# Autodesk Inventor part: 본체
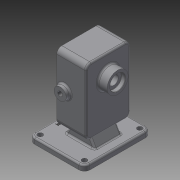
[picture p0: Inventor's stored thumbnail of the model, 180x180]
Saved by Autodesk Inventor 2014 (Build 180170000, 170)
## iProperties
Created: 2020-04
Part Number: 본체
Material: Generic
Document SubType Name: Modeling
Designer: kh
Density: 1 g/cm^3
Appearance: Default
Mass: 544.812 g
Surface Area: 819.925 cm^2
Volume: 544.812 cm^3
Author: kh
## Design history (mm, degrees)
sketch "스케치1"
  geometry: L1 (-50, -60)-(50, -60); L2 (50, -60)-(50, 60); L3 (50, 60)-(-50, 60); L4 (-50, 60)-(-50, -60); L5 (-50, -60)-(50, 60); L6 (50, -60)-(-50, 60); 1 further point
  constraints: 12 end point, 2 midpoint, 2 parallel, 1 horizontal, 1 perpendicular
  dimensions: "d0" = 100 distance of L3.end L2.end; "d1" = 120 distance of L2.end L1.end
extrude "돌출1" new body sketch "스케치1" distance "d2" = 10; taper "d3" = 0 deg
node "작업 평면1"
sketch "스케치3"
  geometry: L1 (-30, 20)-(-150, 20); L2 (-150, 20)-(-150, 100); L3 (-150, 100)-(-30, 100); L4 (-30, 100)-(-30, 20); L5 (-90, 100)-(-90, 20); L6 (0, 60)-(-22.355, 60); L7 (0, 120)-(0, 0) reference; 1 further point
  constraints: 12 end point, 3 midpoint, 2 parallel, 2 perpendicular, 1 horizontal, 1 point on line
  dimensions: "d10" = 120 distance of L2.end L3.end; "d11" = 80 distance of L1.end L2.end; "d12" = 90 distance from line of L7 L5.start
extrude "돌출3" join sketch "스케치3" distance "d13" = 53; taper "d14" = 0 deg
sketch "스케치4"
  geometry: L1 (-30, 20)-(-150, 20) reference; L2 (-30, 100)-(-30, 20) reference; L3 (-150, 100)-(-30, 100) reference; L4 (-150, 20)-(-150, 100) reference; L5 (0, 60)-(-21.925, 60); L6 (-90, 100)-(-90, 20); C1 r 19 at (-112, 60)
  constraints: 4 end point, 2 midpoint, 1 centre point, 1 perpendicular, 1 point on line
  dimensions: "d15" = 38 diameter of C1; "d16" = 22 distance from line of L6 C1.centre
extrude "돌출4" join sketch "스케치4" stored distance "d17" = 53; taper "d18" = 0 deg
sketch "스케치5"
  geometry: L1 (112, 60)-(68, 60); L2 (112, 84)-(68, 84); L3 (68, 36)-(112, 36); C1 r 19 at (112, 60) reference; A1 r 24 centre (112, 60) between (112, 36) and (112, 84); A2 r 24 centre (68, 60) between (68, 84) and (68, 36); 2 further points
  constraints: 8 end point, 4 point on circle, 4 tangent, 2 centre point, 1 horizontal, 1 midpoint, 1 parallel
  dimensions: "d19" = 44 distance of L1.start L1.end; "d20" = 24 radius of A1
extrude "돌출5" cut sketch "스케치5" distance "d21" = 29; taper "d22" = 0 deg
sketch "스케치6"
  geometry: L1 (68, 84)-(112, 84) reference; L2 (112, 36)-(68, 36) reference; C1 r 12.5 at (112, 60); C2 r 12.5 at (68, 60); A1 r 24 centre (68, 60) between (68, 84) and (68, 36) reference; A2 r 24 centre (112, 60) between (112, 36) and (112, 84) reference; 1 further point
  constraints: 2 centre point, 2 coincident
  dimensions: "d23" = 25 diameter of C1; "d24" = 25 diameter of C2
extrude "돌출6" cut sketch "스케치6" distance "d25" = 15; taper "d26" = 0 deg
sketch "스케치8"
  geometry: C1 r 19 at (0, 0) reference; C2 r 14 at (0, 0); 1 further point
  constraints: 1 centre point, 1 coincident
  dimensions: "d28" = 28 diameter of C2
extrude "돌출7" cut sketch "스케치8" distance "d29" = 7.3; taper "d30" = 0 deg
sketch "스케치9"
  geometry: C1 r 14 at (0, 0) reference; C2 r 8.5 at (0, 0); 1 further point
  constraints: 1 centre point, 1 coincident
  dimensions: "d31" = 17 diameter of C2
extrude "돌출8" cut sketch "스케치9" stored distance "d32" = 7.3; taper "d33" = 0 deg
sketch "스케치12"
  geometry: L1 (33, -40)-(33, 40) reference; L2 (33, 40)-(-20, 40) reference; L3 (-20, -40)-(-20, 40) reference; L4 (33, -40)-(-20, -40) reference; L5 (6, -24)-(7, -24); L6 (7, -24)-(7, 24); L7 (7, 24)-(6, 24); L8 (6, 24)-(6, -24); L9 (0, 0)-(-6.48, 0); L10 (6.5, 40)-(6.5, 35.569); 2 further points
  constraints: 12 end point, 3 midpoint, 3 perpendicular, 2 parallel, 2 point on line, 1 horizontal
  dimensions: "d40" = 1 distance of L7.end L6.end; "d41" = 48 distance of L6.end L5.end
extrude "돌출10" join sketch "스케치12" stored distance "d42" = 7.3; taper "d43" = 0 deg
sketch "스케치13"
  geometry: L1 (50, 0)-(-50, 0) reference; L2 (-50, 0)-(-50, 10) reference; L3 (50, 10)-(-50, 10) reference; L4 (50, 0)-(50, 10) reference; L5 (-33, 30)-(-33, 150) reference; L6 (-33, 150)-(20, 150) reference; L7 (20, 30)-(20, 150) reference; L8 (-33, 30)-(20, 30) reference; L9 (20, 10)-(11.709, 24.361); L10 (-33, 10)-(-25.418, 23.132); 1 further point
  constraints: 4 end point, 2 point on line
  dimensions: "d44" = 60 deg angle of L3 L9; "d46" = 60 deg angle of L3 L10; "d47" = 17 distance from line of L10.start L2; "d48" = 53 distance of L9.start L10.start
  node "투영된 루프8"
  node "투영된 루프9"
feature "리브1" dims "d49" = 1, "d50" = 48, "d51" = 0, "d52" = 0, "d53" = 1, "d54" = 1
feature "리브2" dims "d55" = 1, "d56" = 48, "d57" = 0, "d58" = 0, "d59" = 1, "d60" = 1
node "작업 평면3"
sketch "스케치14"
  geometry: L1 (0, 0)-(0, 120) reference; L2 (0, 120)-(-53, 120) reference; L3 (-53, 0)-(-53, 120) reference; L4 (0, 0)-(-53, 0) reference; L5 (-53, 60)-(-47.567, 60); C1 r 11 at (-39, 60); 1 further point
  constraints: 2 end point, 1 centre point, 1 midpoint, 1 parallel, 1 point on line
  dimensions: "d62" = 22 diameter of C1; "d63" = 14 distance from line of C1.centre L3
extrude "돌출11" join sketch "스케치14" stored distance "d64" = 7.3; taper "d65" = 0 deg
sketch "스케치15"
  geometry: C1 r 11 at (0, 0) reference; 2 further points
  constraints: 1 coincident
hole "구멍1" sketch "스케치15" at (0, 0) diameter "d66" = 8.917; stored, may be unused: countersink angle "d70" = 90 deg, drill point angle "d72" = 118 deg; dims "d67" = 6, "d68" = 4, "d69" = 2, "d71" = 8
fillet "모깎기1" dims "d73" = 9
fillet "모깎기2" dims "d74" = 10
sketch "스케치16"
  geometry: L1 (50, -50)-(50, 50) reference; L2 (-40, -60)-(40, -60) reference; L3 (-50, 50)-(-50, -50) reference; L4 (40, 60)-(-40, 60) reference; A1 r 10 centre (40, 50) between (50, 50) and (40, 60) reference; A2 r 10 centre (40, -50) between (40, -60) and (50, -50) reference; A3 r 10 centre (-40, -50) between (-50, -50) and (-40, -60) reference; A4 r 10 centre (-40, 50) between (-40, 60) and (-50, 50) reference; 5 further points
  constraints: 4 coincident
hole "구멍2" sketch "스케치16" at (-40, 50), (40, 50), (40, -50), (-40, -50) diameter "d75" = 9; stored, may be unused: countersink angle "d79" = 90 deg, drill point angle "d81" = 118 deg; dims "d76" = 6, "d77" = 4, "d78" = 2, "d80" = 8
fillet "모깎기3" dims "d82" = 3
fillet "모깎기4" dims "d83" = 3
fillet "모깎기5" dims "d84" = 3
fillet "모깎기6" dims "d85" = 3
chamfer "모따기1" distance "d86" = 0.7; stored, may be unused: second distance "d87" = 2, angle "d88" = 30 deg
fillet "모깎기7" dims "d89" = 0.5
chamfer "모따기2" distance "d90" = 1; stored, may be unused: second distance "d91" = 2, angle "d92" = 30 deg
sketch "스케치17"
  geometry: L1 (-36.998, 20.739)-(-36.998, -20.739); L2 (-36.998, -20.739)-(-43.002, -20.739); L3 (-43.002, -20.739)-(-43.002, 20.739); L4 (-43.002, 20.739)-(-36.998, 20.739); L5 (-43.002, 20.739)-(-36.998, -20.739); L6 (-50, 50)-(-50, -50) reference; L7 (40, 60)-(-40, 60) reference; 2 further points
  constraints: 2 end point, 1 midpoint, 2 other
  dimensions: "d93" = 10 distance from line of point (-40, 0) L6; "d94" = 60 distance from line of point (-40, 0) L7
feature "엠보싱1" sketch "스케치17" dims "d95" = 0.5, "d96" = 0
sketch "스케치18"
  geometry: L1 (68, 84)-(112, 84) reference; L2 (112, 36)-(68, 36) reference; L3 (30, 91)-(30, 29) reference; L4 (39, 20)-(90, 20) reference; L5 (90, 20)-(141, 20) reference; L6 (150, 29)-(150, 91) reference; L7 (141, 100)-(90, 100) reference; L8 (90, 100)-(39, 100) reference; A1 r 24 centre (68, 60) between (68, 84) and (68, 36) reference; A2 r 24 centre (112, 60) between (112, 36) and (112, 84) reference; A3 r 9 centre (39, 91) between (39, 100) and (30, 91) reference; A4 r 9 centre (39, 29) between (30, 29) and (39, 20) reference; A5 r 9 centre (141, 29) between (141, 20) and (150, 29) reference; A6 r 9 centre (141, 91) between (150, 91) and (141, 100) reference; 2 further points
  constraints: 1 coincident
hole "구멍3" sketch "스케치18" at (141, 91) diameter "d97" = 4.459; stored, may be unused: countersink angle "d101" = 90 deg, drill point angle "d103" = 118 deg; dims "d98" = 10, "d99" = 4, "d100" = 2, "d102" = 12
node "작업 평면4"
node "솔리드1"
mirror "대칭1"
pattern_linear "직사각형 패턴1" dims "d106" = 62, "d109" = 29
mirror "대칭2"
node "투영된 루프1"
node "투영된 루프2"
node "투영된 루프4"
node "투영된 루프5"
node "투영된 루프7"
node "투영된 루프10"
node "투영된 루프11"
node "투영된 루프12"
node "투영된 루프13"
other parameters: "d9" = -17, "d61" = 8
